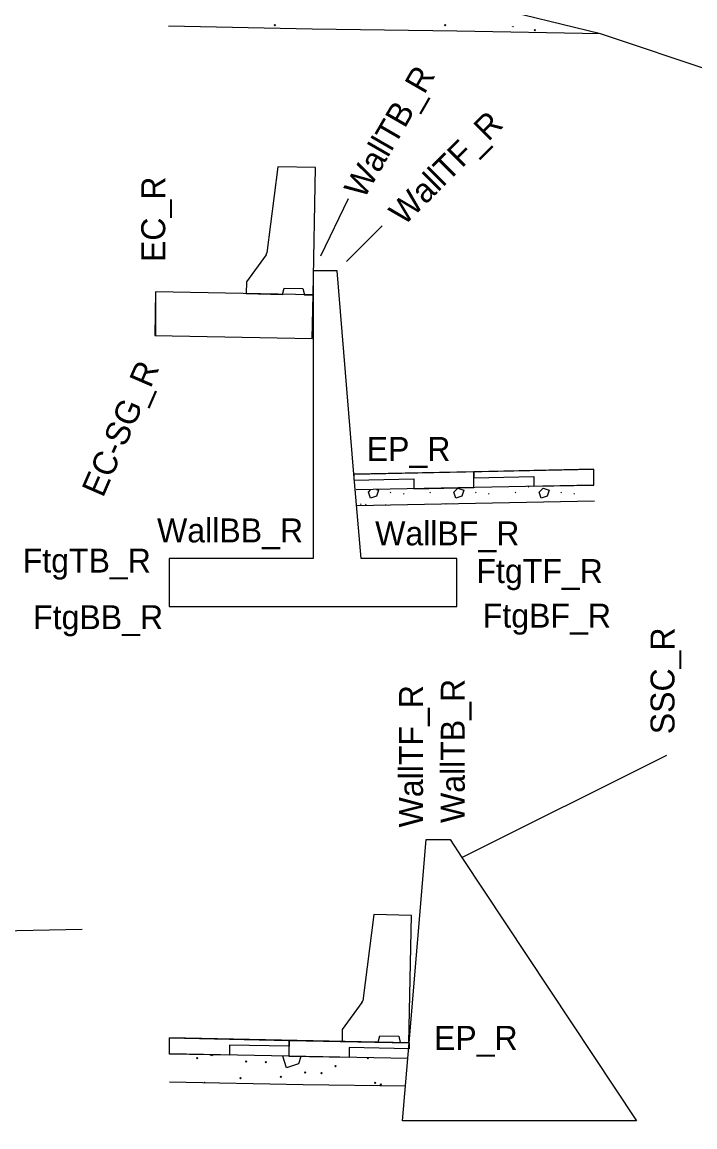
# Model space of a CAD drawing. Extents: x 0 to 1.42, y 0 to 0.92.
# Drawn here: x 0.6404 to 0.8743, y 0.3166 to 0.7008 of the extents above; entities that cross this region are included whole.
import ezdxf

# ---------------------------------------------------------------- set-up
doc = ezdxf.new("R2010")
doc.units = 0
for name, color, linetype in [('Level 14', 7, 'Continuous'), ('Level 63', 7, 'Continuous'), ('P_RDWY_PLAN_Detail', 7, 'Continuous'), ('P_RDWY_PLAN_DetailTx', 7, 'Continuous')]:
    doc.layers.add(name, color=color, linetype=linetype)

msp = doc.modelspace()

# ---------------------------------------------------------------- linework, layer by layer
at = {"layer": 'Level 14'}
for points in [[(0.7415455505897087, 0.6058696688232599), (0.7424312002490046, 0.6501521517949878), (0.7293104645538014, 0.6504145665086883), (0.7254686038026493, 0.6204821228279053)], [(0.725220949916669, 0.6198581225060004), (0.7183929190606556, 0.6104345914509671), (0.7183109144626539, 0.6063343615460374), (0.7308849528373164, 0.6060828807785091), (0.7314753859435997, 0.6082587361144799), (0.738035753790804, 0.6081275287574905), (0.7385387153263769, 0.6059298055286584), (0.7415455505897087, 0.6058696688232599)], [(0.774863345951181, 0.3458352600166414), (0.7757489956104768, 0.3901177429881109), (0.7626282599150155, 0.39038015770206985), (0.7587863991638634, 0.36044771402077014)], [(0.7585387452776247, 0.35982371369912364), (0.7517107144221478, 0.3504001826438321), (0.7516287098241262, 0.34629995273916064), (0.7642027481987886, 0.3460484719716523), (0.7647931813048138, 0.3482243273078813), (0.7713535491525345, 0.3480931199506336), (0.771856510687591, 0.34589539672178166), (0.774863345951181, 0.3458352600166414)]]:
    msp.add_lwpolyline(points, dxfattribs=at)
for centre, radius, start, end in [((0.724113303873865, 0.620658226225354), 0.0013670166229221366, 324.07640660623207, 352.68406216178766), ((0.7574310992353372, 0.3606238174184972), 0.001367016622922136, 324.0764066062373, 352.6840621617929)]:
    msp.add_arc(centre, radius, start, end, dxfattribs=at)
at = {"layer": 'Level 63'}
msp.add_lwpolyline([(0.7415455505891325, 0.6058696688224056), (0.6867815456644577, 0.606964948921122), (0.6864776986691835, 0.5917725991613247), (0.7412417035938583, 0.5906773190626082)], close=True, dxfattribs=at)
at = {"layer": 'P_RDWY_PLAN_Detail'}
for p, q in [((0.7279580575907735, 0.6998965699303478), (0.7284226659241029, 0.6994319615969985)), ((0.7284226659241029, 0.6998965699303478), (0.7279580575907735, 0.6994319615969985)), ((0.7872729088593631, 0.6998965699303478), (0.7877375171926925, 0.6994319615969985)), ((0.7877375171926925, 0.6998965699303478), (0.7872729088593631, 0.6994319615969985)), ((0.8107789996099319, 0.6991774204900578), (0.8108591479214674, 0.6990972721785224)), ((0.8112436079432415, 0.6991774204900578), (0.811158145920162, 0.6990919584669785)), ((0.818401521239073, 0.6981930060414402), (0.8188661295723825, 0.6977283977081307)), ((0.8188661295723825, 0.6981930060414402), (0.818401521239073, 0.6977283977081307)), ((0.7498788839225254, 0.6142030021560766), (0.741545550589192, 0.6142030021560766)), ((0.741545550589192, 0.6142030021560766), (0.741545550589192, 0.6058696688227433)), ((0.7557642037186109, 0.5435791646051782), (0.7498788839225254, 0.6142030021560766)), ((0.6867815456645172, 0.6069649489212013), (0.6867815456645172, 0.5917665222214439)), ((0.741545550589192, 0.6058696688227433), (0.6867815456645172, 0.6069649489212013)), ((0.741545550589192, 0.6058696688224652), (0.741545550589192, 0.5142030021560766)), ((0.7557642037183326, 0.5435791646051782), (0.8390975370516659, 0.5452458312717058)), ((0.7582122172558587, 0.5142030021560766), (0.7557642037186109, 0.54357916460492)), ((0.8163660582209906, 0.5392486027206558), (0.8165983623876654, 0.5390162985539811)), ((0.8165983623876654, 0.5392486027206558), (0.8163660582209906, 0.5390162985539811)), ((0.7683566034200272, 0.5372352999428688), (0.7685889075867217, 0.5370029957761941)), ((0.7685889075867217, 0.5372352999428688), (0.7683566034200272, 0.5370029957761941)), ((0.7729252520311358, 0.5368481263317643), (0.7731575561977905, 0.5366158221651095)), ((0.7731575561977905, 0.5368481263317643), (0.7729252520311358, 0.5366158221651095)), ((0.7821399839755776, 0.5373127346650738), (0.7823722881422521, 0.537080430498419)), ((0.7823722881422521, 0.5373127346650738), (0.7821399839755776, 0.537080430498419)), ((0.7980140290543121, 0.5372352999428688), (0.7982463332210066, 0.5370029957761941)), ((0.7982463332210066, 0.5372352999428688), (0.7980140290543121, 0.5370029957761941)), ((0.8025826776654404, 0.5368481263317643), (0.8028149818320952, 0.5366158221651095)), ((0.8028149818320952, 0.5368481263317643), (0.8025826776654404, 0.5366158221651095)), ((0.8117974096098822, 0.5373127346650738), (0.812029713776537, 0.537080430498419)), ((0.812029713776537, 0.5373127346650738), (0.8117974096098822, 0.537080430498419)), ((0.8276714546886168, 0.5372352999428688), (0.8279037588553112, 0.5370029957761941)), ((0.8279037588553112, 0.5372352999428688), (0.8276714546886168, 0.5370029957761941)), ((0.8322401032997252, 0.5368481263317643), (0.8324724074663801, 0.5366158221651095)), ((0.8324724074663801, 0.5368481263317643), (0.8322401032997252, 0.5366158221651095)), ((0.7579804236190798, 0.5332861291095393), (0.7582127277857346, 0.5330538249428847)), ((0.7582127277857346, 0.5332861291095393), (0.7579804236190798, 0.5330538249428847)), ((0.759761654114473, 0.5331312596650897), (0.7599939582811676, 0.5328989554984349)), ((0.7599939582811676, 0.5331312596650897), (0.759761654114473, 0.5328989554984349)), ((0.7667307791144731, 0.5329763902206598), (0.7669627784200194, 0.532744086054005)), ((0.7669627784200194, 0.5329763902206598), (0.7667307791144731, 0.532744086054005)), ((0.7876378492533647, 0.5332861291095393), (0.7877932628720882, 0.5331307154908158)), ((0.7878701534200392, 0.5332861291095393), (0.7877131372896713, 0.5331291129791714)), ((0.741545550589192, 0.5142030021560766), (0.6915455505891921, 0.5142030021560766)), ((0.6915455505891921, 0.5142030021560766), (0.6915455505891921, 0.4975363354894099)), ((0.7915455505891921, 0.5142030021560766), (0.7582122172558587, 0.5142030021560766)), ((0.7915455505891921, 0.4975363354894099), (0.7915455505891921, 0.5142030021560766)), ((0.6915455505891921, 0.4975363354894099), (0.7915455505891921, 0.4975363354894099)), ((0.7933130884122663, 0.41019898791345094), (0.8645667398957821, 0.4458258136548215)), ((0.7749447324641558, 0.3458336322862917), (0.7808300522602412, 0.4164574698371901)), ((0.7808300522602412, 0.4164574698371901), (0.7891633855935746, 0.4164574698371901)), ((0.7749447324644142, 0.3458336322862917), (0.6916113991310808, 0.34750029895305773)), ((0.7010275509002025, 0.34070641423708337), (0.7014921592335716, 0.3402418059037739)), ((0.7014921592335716, 0.34070641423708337), (0.7010275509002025, 0.3402418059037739)), ((0.7179922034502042, 0.3395747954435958), (0.7184568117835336, 0.3391101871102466)), ((0.7184568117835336, 0.3395747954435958), (0.7179922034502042, 0.3391101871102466)), ((0.7248768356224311, 0.3393125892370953), (0.7253414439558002, 0.338847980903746)), ((0.7253414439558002, 0.3393125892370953), (0.7248768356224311, 0.338847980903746)), ((0.7607009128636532, 0.3406003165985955), (0.7603424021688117, 0.3402418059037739)), ((0.7604436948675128, 0.3406051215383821), (0.7608070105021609, 0.3402418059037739)), ((0.7385903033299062, 0.3357030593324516), (0.7390549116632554, 0.33523845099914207)), ((0.7390549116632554, 0.3357030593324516), (0.7385903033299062, 0.33523845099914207)), ((0.7442355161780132, 0.3354408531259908), (0.7447001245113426, 0.33497624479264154)), ((0.7447001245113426, 0.3354408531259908), (0.7442355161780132, 0.33497624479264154)), ((0.7491208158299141, 0.33787123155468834), (0.7495854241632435, 0.337406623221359)), ((0.7495854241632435, 0.33787123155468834), (0.7491208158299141, 0.337406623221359)), ((0.7035893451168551, 0.33214106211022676), (0.7037729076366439, 0.33195749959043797)), ((0.7040539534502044, 0.33214106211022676), (0.7038687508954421, 0.33195585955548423)), ((0.7160492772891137, 0.3337372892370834), (0.716513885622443, 0.3332726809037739)), ((0.716513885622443, 0.3337372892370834), (0.7160492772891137, 0.3332726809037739)), ((0.7300724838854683, 0.33415436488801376), (0.7305370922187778, 0.3336897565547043)), ((0.7305370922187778, 0.33415436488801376), (0.7300724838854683, 0.3336897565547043)), ((0.7629041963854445, 0.33214106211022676), (0.7633688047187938, 0.33167645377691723)), ((0.7633688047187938, 0.33214106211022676), (0.7629041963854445, 0.33167645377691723)), ((0.7648336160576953, 0.33156911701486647), (0.7652982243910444, 0.33110450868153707)), ((0.7652982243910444, 0.33156911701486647), (0.7648336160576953, 0.33110450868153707))]:
    msp.add_line(p, q, dxfattribs=at)
for points in [[(0.8810170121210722, 0.6834707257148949), (0.8414791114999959, 0.6966500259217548), (0.7748124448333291, 0.712983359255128), (0.7414791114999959, 0.7136500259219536), (0.6914791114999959, 0.714650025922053)], [(0.8414791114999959, 0.6966500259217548), (0.7914791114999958, 0.6976500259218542), (0.7412747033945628, 0.6983194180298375), (0.6912747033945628, 0.6993194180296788)], [(0.8390975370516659, 0.5397458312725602), (0.7564650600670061, 0.5380931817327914)], [(0.7635756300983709, 0.5382353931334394), (0.7642528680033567, 0.5380096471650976), (0.7635559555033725, 0.5359189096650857), (0.7614652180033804, 0.5352219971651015), (0.7607683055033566, 0.5373127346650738), (0.7616525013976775, 0.5381969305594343)], [(0.8393192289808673, 0.5341612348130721), (0.7566867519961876, 0.5325085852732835)], [(0.7891633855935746, 0.4164574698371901), (0.7933130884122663, 0.41019898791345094)], [(0.7933130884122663, 0.41019898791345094), (0.8540002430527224, 0.3186720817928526), (0.772681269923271, 0.3186720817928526), (0.7749447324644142, 0.3458336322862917)], [(0.08341356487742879, 0.3083502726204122), (0.09362096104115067, 0.31286508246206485), (0.14012781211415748, 0.3246763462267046), (0.18146723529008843, 0.3268909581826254), (0.2102571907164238, 0.31877071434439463), (0.2715281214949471, 0.32246173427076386), (0.3084383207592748, 0.3261527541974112), (0.35642157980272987, 0.31877071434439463), (0.44858000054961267, 0.3226958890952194), (0.5702261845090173, 0.38351898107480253), (0.6613119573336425, 0.3853406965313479)], [(0.7744871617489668, 0.3403427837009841), (0.6916113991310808, 0.34200029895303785)], [(0.7070403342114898, 0.3416027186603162), (0.7060672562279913, 0.34127835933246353), (0.7059523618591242, 0.3416230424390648)], [(0.7373249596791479, 0.341036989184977), (0.7364920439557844, 0.33853824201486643), (0.7323105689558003, 0.3371444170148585), (0.7309734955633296, 0.34115563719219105)], [(0.7736886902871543, 0.3307611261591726), (0.7381283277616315, 0.33123526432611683), (0.6916113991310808, 0.3321656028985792)]]:
    msp.add_lwpolyline(points, dxfattribs=at)
for points in [[(0.7974308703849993, 0.5444124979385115), (0.7557642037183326, 0.5435791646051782), (0.7557642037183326, 0.541494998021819), (0.7765975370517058, 0.5419116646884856), (0.776597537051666, 0.5384958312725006), (0.7974308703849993, 0.5389124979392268)], [(0.8390975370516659, 0.5452458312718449), (0.7974308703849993, 0.5444124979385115), (0.7974308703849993, 0.5423283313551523), (0.8182642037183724, 0.542744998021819), (0.8182642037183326, 0.5393291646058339), (0.8390975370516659, 0.5397458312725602)], [(0.7911226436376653, 0.5352219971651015), (0.7904257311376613, 0.5373127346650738), (0.7918195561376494, 0.5387065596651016), (0.7939102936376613, 0.5380096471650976), (0.7932133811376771, 0.5359189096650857)], [(0.8207800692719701, 0.5352219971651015), (0.8200831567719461, 0.5373127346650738), (0.821476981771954, 0.5387065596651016), (0.823567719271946, 0.5380096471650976), (0.822870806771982, 0.5359189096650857)], [(0.6916113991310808, 0.34750029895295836), (0.7332780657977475, 0.346666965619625), (0.7332780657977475, 0.34458279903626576), (0.7124447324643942, 0.34499946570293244), (0.7124447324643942, 0.3414742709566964), (0.6916113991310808, 0.3418909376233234)], [(0.7332780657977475, 0.346666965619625), (0.7749447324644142, 0.3458336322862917), (0.7749447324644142, 0.3437494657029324), (0.754111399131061, 0.34416613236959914), (0.754111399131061, 0.3406409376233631), (0.7332780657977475, 0.34105760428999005)]]:
    msp.add_lwpolyline(points, close=True, dxfattribs=at)
at = {"layer": 'P_RDWY_PLAN_DetailTx'}
for p, q in [((0.7537183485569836, 0.639276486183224), (0.7440656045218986, 0.6193937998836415)), ((0.7656069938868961, 0.6299311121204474), (0.7531631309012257, 0.6174872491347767))]:
    msp.add_line(p, q, dxfattribs=at)

# ---------------------------------------------------------------- texts
for s, rotation, p in [('WallTB_R', 59.99999846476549, (0.7591658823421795, 0.6388884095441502)), ('WallTF_R', 44.999998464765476, (0.7731310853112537, 0.6296436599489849)), ('EC_R', 89.99999846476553, (0.6901449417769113, 0.6173071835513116)), ('EC-SG_R', 66.51656923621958, (0.6685010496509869, 0.5351118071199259)), ('WallBB_R', 359.99999846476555, (0.6873077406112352, 0.5198240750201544)), ('WallBF_R', 359.99999846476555, (0.7631211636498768, 0.5187856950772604)), ('SSC_R', 89.99999846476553, (0.8671879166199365, 0.4531043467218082)), ('WallTF_R', 89.99999846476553, (0.7797523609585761, 0.4207088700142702)), ('WallTB_R', 89.99999846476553, (0.7942769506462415, 0.42224477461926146))]:
    msp.add_text(s, height=0.008330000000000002, rotation=rotation, dxfattribs=at).set_placement(p)
for s, p in [('EP_R', (0.7601789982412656, 0.5481500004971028)), ('FtgTB_R', (0.6405923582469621, 0.5093367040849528)), ('FtgTF_R', (0.7983314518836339, 0.5056860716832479)), ('FtgBB_R', (0.6442172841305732, 0.4896485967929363)), ('FtgBF_R', (0.8005460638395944, 0.49018378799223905)), ('EP_R', (0.7835499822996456, 0.3433570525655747))]:
    msp.add_text(s, height=0.008330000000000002, dxfattribs=at).set_placement(p)

doc.saveas('drawing.dxf')
